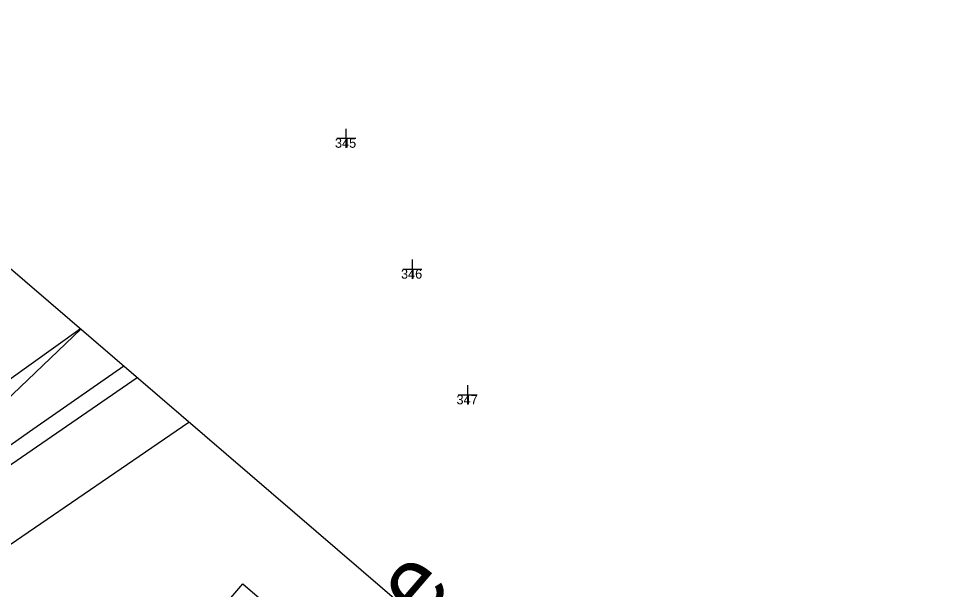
# Model space of a CAD drawing. Extents: x -540141 to -537502, y -1044527 to -1042580.
# Drawn here: x -538114.6 to -538066.09, y -1042707.09 to -1042677.11 of the extents above; entities that cross this region are included whole.
import ezdxf

# ---------------------------------------------------------------- set-up
doc = ezdxf.new("R2010")
doc.units = 0
for name, color, linetype in [('Hranice parcel', 7, 'Continuous'), ('Implicitní', 7, 'Continuous'), ('Nová vrstva (0)', 7, 'Continuous'), ('Vrstva 1', 7, 'Continuous'), ('čísla bodu', 7, 'Continuous')]:
    doc.layers.add(name, color=color, linetype=linetype)

msp = doc.modelspace()

# ---------------------------------------------------------------- linework, layer by layer
at = {"layer": 'Hranice parcel'}
msp.add_line((-538125.38, -1042706.8), (-538111.324, -1042693.419), dxfattribs=at)
msp.add_lwpolyline([(-538109.065, -1042695.357), (-538114.03, -1042698.81), (-538125.38, -1042706.8)], dxfattribs=at)
at = {"layer": 'Implicitní'}
msp.add_lwpolyline([(-538501.178, -1043011.131), (-538178.778, -1042635.521), (-538066.095, -1042732.24), (-538388.495, -1043107.851)], close=True, dxfattribs=at)
at = {"layer": 'Nová vrstva (0)'}
msp.add_lwpolyline([(-538159.802, -1042773.183), (-538102.812, -1042706.787), (-538072.46, -1042732.84), (-538129.45, -1042799.236)], close=True, dxfattribs=at)
at = {"layer": 'Vrstva 1'}
for points in [[(-538111.351, -1042693.395), (-538136.797, -1042711.607), (-538172.989, -1042726.797), (-538208.83, -1042740.615), (-538205.619, -1042745.158), (-538203.899, -1042749.125), (-538170.336, -1042731.349), (-538134.844, -1042718.248), (-538105.643, -1042698.295)], [(-538205.619, -1042745.158), (-538170.294, -1042730.099), (-538135.796, -1042714.827), (-538108.375, -1042695.95)]]:
    msp.add_lwpolyline(points, dxfattribs=at)
at = {"layer": 'čísla bodu'}
for p, q in [((-538097.382, -1042683.898), (-538097.382, -1042682.898)), ((-538097.882, -1042683.398), (-538096.882, -1042683.398)), ((-538097.382, -1042683.398), (-538097.382, -1042683.398)), ((-538093.898, -1042690.77), (-538093.898, -1042689.77)), ((-538094.398, -1042690.27), (-538093.398, -1042690.27)), ((-538093.898, -1042690.27), (-538093.898, -1042690.27)), ((-538090.996, -1042697.368), (-538090.996, -1042696.368)), ((-538091.496, -1042696.868), (-538090.496, -1042696.868)), ((-538090.996, -1042696.868), (-538090.996, -1042696.868))]:
    msp.add_line(p, q, dxfattribs=at)

# ---------------------------------------------------------------- texts
at = {"layer": 'Nová vrstva (0)'}
msp.add_text('groprojekce', height=3.60691, rotation=49.3593, dxfattribs=at).set_placement((-538108.163, -1042726.034))
at = {"layer": 'čísla bodu'}
for s, p in [('345', (-538097.972, -1042683.898)), ('346', (-538094.502, -1042690.77)), ('347', (-538091.586, -1042697.368))]:
    msp.add_text(s, height=0.5, rotation=360, dxfattribs=at).set_placement(p)

doc.saveas('drawing.dxf')
